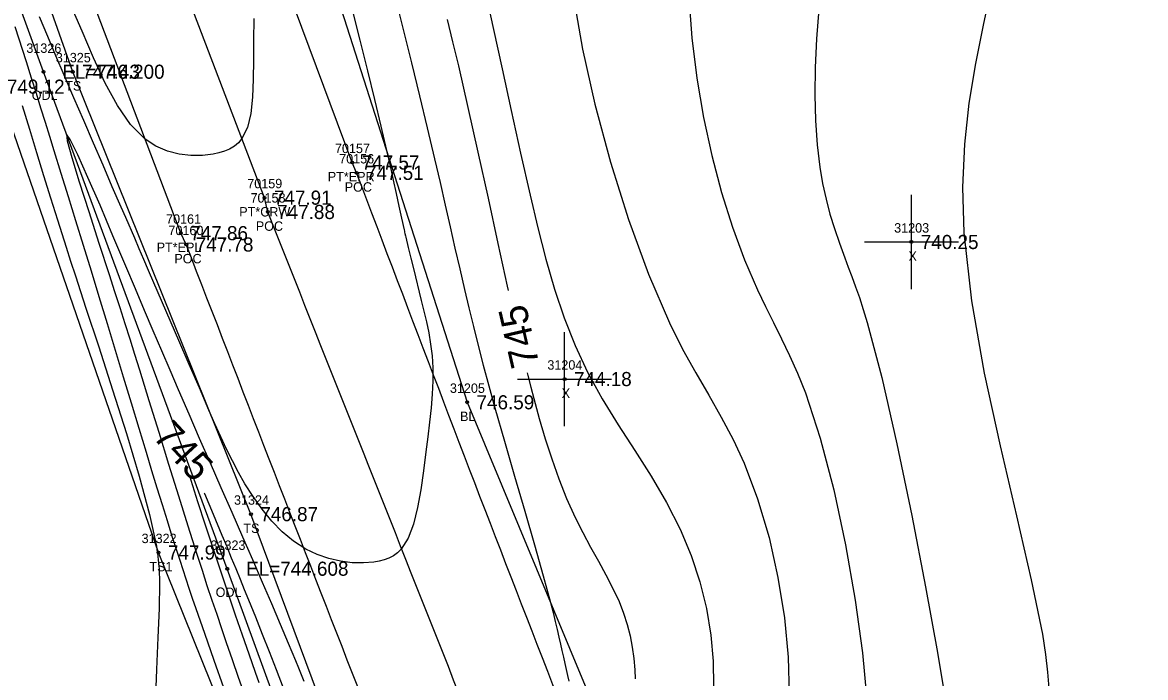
# Model space of a CAD drawing. Extents: x 1376587 to 1378239, y 1000335 to 1003031.
# Drawn here: x 1376751 to 1376870.4, y 1002682.8 to 1002752.4 of the extents above; entities that cross this region are included whole.
import ezdxf

# ---------------------------------------------------------------- set-up
doc = ezdxf.new("R2010")
doc.units = 0
for name, color, linetype in [('RD_DTM_BkLn1', 7, 'Continuous'), ('RD_DTM_BkLn2', 7, 'Continuous'), ('RD_DTM_BkLn_txCode', 7, 'Continuous'), ('RD_DTM_Major1', 7, 'Continuous'), ('RD_DTM_Major1_Lbl', 7, 'Continuous'), ('RD_DTM_Minor1', 7, 'Continuous'), ('RD_EX_H2O', 7, 'Continuous'), ('RD_EX_H2O_txCode', 7, 'Continuous'), ('RD_EX_Misc', 7, 'Continuous'), ('RD_EX_Misc_txCode', 7, 'Continuous'), ('RD_EX_Road', 7, 'Continuous'), ('RD_EX_Road_txCode', 7, 'Continuous'), ('RD_EX_TX_H2O_ELEV', 7, 'Continuous'), ('RD_EX_TX_Misc_ELEV', 7, 'Continuous'), ('RD_EX_TX_Road_ELEV', 7, 'Continuous'), ('RD_HC_Survey_ELEV', 7, 'Continuous'), ('RD_HC_Survey_txCode', 7, 'Continuous'), ('RD_SMD_Locator', 7, 'Continuous')]:
    doc.layers.add(name, color=color, linetype=linetype)

msp = doc.modelspace()

# ---------------------------------------------------------------- linework, layer by layer
at = {"layer": 'RD_DTM_BkLn1'}
for points in [[(1376777.12, 1002732.3), (1376776.77, 1002733.82), (1376754.91, 1002791.11), (1376734.25, 1002847.87), (1376712.48, 1002906.61), (1376690.98, 1002965.02), (1376668.66, 1003026.02)], [(1376775.36, 1002784.46), (1376784.04, 1002756.66), (1376798.31, 1002712.07), (1376818.41, 1002663.8), (1376823.91, 1002650.38)]]:
    msp.add_lwpolyline(points, dxfattribs=at)
msp.add_spline([(1377003.45, 1002259.31), (1376973.19, 1002311.2), (1376942.72, 1002364.73), (1376914.25, 1002420.14), (1376886.11, 1002475.59), (1376860.06, 1002531.09), (1376835.65, 1002585.09), (1376813.12, 1002641.26), (1376777.12, 1002732.3)], degree=3, dxfattribs=at)
at = {"layer": 'RD_DTM_BkLn2'}
for points in [[(1376885.61, 1002428.98), (1376889.78, 1002434.68), (1376874.69, 1002468.75), (1376852.19, 1002514.33), (1376831.8, 1002561.56), (1376809.96, 1002613.35), (1376792.97, 1002652.8), (1376775.33, 1002700.18), (1376756.39, 1002747.21), (1376739.8, 1002794.07), (1376723.1, 1002839.91), (1376704.95, 1002887.54), (1376687.77, 1002934.36), (1376670.41, 1002980.85)], [(1376885.61, 1002428.97), (1376881.3, 1002430.18), (1376863.13, 1002464.59), (1376838.71, 1002510.16), (1376821.82, 1002559.18), (1376802.89, 1002607.61), (1376786.81, 1002643.28), (1376765.51, 1002696.1), (1376748.39, 1002745.62), (1376732.07, 1002790.52), (1376713.54, 1002837.08), (1376692.71, 1002883.81), (1376675.42, 1002930.22), (1376657.29, 1002975.68)]]:
    msp.add_lwpolyline(points, dxfattribs=at)
at = {"layer": 'RD_DTM_Major1'}
for points in [[(1376854.11, 1002756.65), (1376853.2, 1002752.32), (1376852.36, 1002748.09), (1376851.65, 1002743.86), (1376851.16, 1002739.51), (1376850.95, 1002734.95), (1376851.09, 1002730.07), (1376851.91, 1002722.84), (1376853.28, 1002715.18), (1376854.96, 1002707.44), (1376856.71, 1002700), (1376858.28, 1002693.2), (1376859.46, 1002687.41), (1376859.79, 1002685.27), (1376860.01, 1002683.37), (1376860.13, 1002681.68)], [(1376796.2, 1002752.76), (1376796.77, 1002750.39), (1376797.38, 1002747.84), (1376798.39, 1002743.42), (1376799.45, 1002738.66), (1376800.53, 1002733.78), (1376801.59, 1002728.96), (1376802.58, 1002724.43), (1376802.69, 1002723.97)], [(1376804.69, 1002715.2), (1376804.76, 1002714.93), (1376805.07, 1002713.69), (1376805.39, 1002712.46), (1376805.97, 1002710.34), (1376806.61, 1002708.19), (1376807.3, 1002706.05), (1376808.06, 1002703.92), (1376808.89, 1002701.85), (1376809.79, 1002699.84), (1376810.6, 1002698.23), (1376811.44, 1002696.68), (1376812.27, 1002695.18), (1376813.07, 1002693.72), (1376813.81, 1002692.29), (1376814.46, 1002690.88), (1376814.94, 1002689.66), (1376815.32, 1002688.44), (1376815.63, 1002687.24), (1376815.86, 1002686.03), (1376816.03, 1002684.83), (1376816.14, 1002683.63), (1376816.18, 1002682.66)], [(1376768.87, 1002704.05), (1376768.94, 1002703.78), (1376769.66, 1002701.53), (1376770.47, 1002699.04), (1376771.31, 1002696.48), (1376772.13, 1002694.05), (1376772.91, 1002691.72), (1376773.67, 1002689.49), (1376774.41, 1002687.36), (1376775.11, 1002685.32), (1376775.78, 1002683.38), (1376776.16, 1002682.27)], [(1376778.8, 1002681.68), (1376778.04, 1002683.64), (1376777.29, 1002685.54), (1376776.56, 1002687.4), (1376775.84, 1002689.22), (1376775.11, 1002691.04), (1376774.66, 1002692.13), (1376774.21, 1002693.24), (1376773.75, 1002694.36), (1376773.28, 1002695.51), (1376772.79, 1002696.69), (1376772.28, 1002697.92), (1376771.35, 1002700.14), (1376770.42, 1002702.33), (1376770.39, 1002702.4)]]:
    msp.add_lwpolyline(points, dxfattribs=at)
at = {"layer": 'RD_DTM_Minor1'}
for points in [[(1376790.63, 1002755.26), (1376791.5, 1002751.71), (1376792.38, 1002748.16), (1376793.24, 1002744.66), (1376794.07, 1002741.24), (1376794.85, 1002737.95), (1376795.43, 1002735.45), (1376795.98, 1002733.04), (1376796.51, 1002730.72), (1376797.02, 1002728.46), (1376797.52, 1002726.25), (1376798.03, 1002724.07), (1376798.49, 1002722.12), (1376798.98, 1002720.14), (1376799.49, 1002718.12), (1376800.03, 1002716.02), (1376800.63, 1002713.82), (1376801.27, 1002711.48), (1376802.28, 1002707.93), (1376803.35, 1002704.22), (1376804.43, 1002700.49), (1376805.47, 1002696.9), (1376806.4, 1002693.62), (1376807.17, 1002690.8), (1376807.44, 1002689.73), (1376807.68, 1002688.77), (1376807.89, 1002687.9), (1376808.07, 1002687.1), (1376808.24, 1002686.37), (1376808.39, 1002685.67), (1376808.54, 1002684.98), (1376808.69, 1002684.31), (1376808.83, 1002683.66), (1376808.97, 1002683.03), (1376809.11, 1002682.42)], [(1376800.3, 1002755.46), (1376801.11, 1002751.7), (1376802.02, 1002747.51), (1376802.99, 1002743.07), (1376803.99, 1002738.54), (1376805, 1002734.1), (1376805.84, 1002730.6), (1376806.69, 1002727.27), (1376807.61, 1002724.09), (1376808.63, 1002721.05), (1376809.78, 1002718.11), (1376811.11, 1002715.27), (1376812.67, 1002712.45), (1376814.37, 1002709.69), (1376816.13, 1002706.95), (1376817.87, 1002704.2), (1376819.51, 1002701.42), (1376820.97, 1002698.57), (1376822.12, 1002695.8), (1376823.04, 1002692.98), (1376823.74, 1002690.14), (1376824.21, 1002687.32), (1376824.46, 1002684.56), (1376824.51, 1002681.88)], [(1376775.65, 1002752.85), (1376775.6, 1002750.53), (1376775.6, 1002748.44), (1376775.58, 1002746.41), (1376775.5, 1002744.49), (1376775.31, 1002742.76), (1376774.96, 1002741.27), (1376774.38, 1002740.1), (1376774, 1002739.65), (1376773.57, 1002739.28), (1376773.07, 1002738.99), (1376772.53, 1002738.76), (1376771.93, 1002738.58), (1376771.3, 1002738.44), (1376770.17, 1002738.31), (1376768.96, 1002738.3), (1376767.71, 1002738.44), (1376766.46, 1002738.76), (1376765.24, 1002739.29), (1376764.08, 1002740.04), (1376762.53, 1002741.6), (1376761.14, 1002743.62), (1376759.85, 1002746.01), (1376758.61, 1002748.67), (1376757.38, 1002751.51), (1376756.11, 1002754.43)], [(1376809.65, 1002754.92), (1376810.58, 1002749.61), (1376811.9, 1002743.75), (1376813.55, 1002737.61), (1376815.47, 1002731.49), (1376817.58, 1002725.69), (1376819.82, 1002720.5), (1376821.21, 1002717.73), (1376822.61, 1002715.2), (1376823.99, 1002712.81), (1376825.32, 1002710.48), (1376826.59, 1002708.1), (1376827.76, 1002705.59), (1376829.19, 1002701.79), (1376830.4, 1002697.7), (1376831.35, 1002693.44), (1376832.04, 1002689.14), (1376832.44, 1002684.96), (1376832.53, 1002681.02)], [(1376821.87, 1002755.12), (1376822.19, 1002750.82), (1376822.71, 1002746.51), (1376823.42, 1002742.35), (1376824.32, 1002738.29), (1376825.36, 1002734.38), (1376826.53, 1002730.67), (1376827.81, 1002727.21), (1376829.16, 1002724.04), (1376830.01, 1002722.26), (1376830.87, 1002720.54), (1376831.73, 1002718.83), (1376832.59, 1002717.06), (1376833.44, 1002715.17), (1376834.27, 1002713.09), (1376835.85, 1002708.26), (1376837.28, 1002702.75), (1376838.53, 1002696.9), (1376839.56, 1002691.02), (1376840.32, 1002685.43), (1376840.79, 1002680.44)], [(1376786.07, 1002753.94), (1376786.91, 1002750.55), (1376787.71, 1002747.31), (1376788.46, 1002744.25), (1376789.14, 1002741.41), (1376789.75, 1002738.82), (1376790.12, 1002737.19), (1376790.45, 1002735.68), (1376790.76, 1002734.27), (1376791.05, 1002732.92), (1376791.33, 1002731.64), (1376791.61, 1002730.4), (1376791.64, 1002730.27), (1376791.67, 1002730.14), (1376791.7, 1002730.01), (1376791.75, 1002729.76), (1376791.78, 1002729.63), (1376792.05, 1002728.51), (1376792.32, 1002727.4), (1376792.6, 1002726.28), (1376793.44, 1002722.9), (1376793.72, 1002721.77), (1376793.99, 1002720.61), (1376794.23, 1002719.44), (1376794.43, 1002718.24), (1376794.58, 1002717), (1376794.66, 1002715.73), (1376794.67, 1002714.36), (1376794.6, 1002712.95), (1376794.48, 1002711.49), (1376794.32, 1002709.97), (1376794.13, 1002708.41), (1376793.92, 1002706.8), (1376793.67, 1002704.79), (1376793.39, 1002702.78), (1376793.04, 1002700.87), (1376792.6, 1002699.12), (1376792.03, 1002697.62), (1376791.29, 1002696.46), (1376790.9, 1002696.07), (1376790.47, 1002695.76), (1376790, 1002695.51), (1376789.5, 1002695.32), (1376788.97, 1002695.18), (1376788.4, 1002695.08), (1376787.28, 1002694.99), (1376786.1, 1002695.02), (1376784.86, 1002695.17), (1376783.61, 1002695.46), (1376782.37, 1002695.88), (1376781.17, 1002696.45), (1376779.87, 1002697.29), (1376778.66, 1002698.3), (1376777.54, 1002699.45), (1376776.51, 1002700.7), (1376775.56, 1002702.04), (1376774.7, 1002703.41), (1376774.01, 1002704.61), (1376773.36, 1002705.84), (1376772.74, 1002707.1), (1376772.13, 1002708.41), (1376771.51, 1002709.79), (1376770.87, 1002711.24), (1376769.85, 1002713.59), (1376768.77, 1002716.08), (1376767.67, 1002718.65), (1376765.48, 1002723.72), (1376764.46, 1002726.09), (1376763.95, 1002727.26), (1376763.46, 1002728.39), (1376762.98, 1002729.5), (1376762.03, 1002731.7), (1376761.54, 1002732.82), (1376760.59, 1002734.99), (1376759.61, 1002737.26), (1376758.59, 1002739.61), (1376757.56, 1002742.01), (1376756.52, 1002744.42), (1376755.49, 1002746.83), (1376754.61, 1002748.91), (1376753.73, 1002750.97), (1376752.86, 1002753.04)], [(1376835.7, 1002753.87), (1376835.45, 1002750.7), (1376835.31, 1002747.66), (1376835.27, 1002744.77), (1376835.33, 1002742.02), (1376835.51, 1002739.45), (1376835.79, 1002737.06), (1376836.09, 1002735.32), (1376836.46, 1002733.67), (1376836.88, 1002732.08), (1376837.36, 1002730.53), (1376837.88, 1002728.99), (1376838.45, 1002727.43), (1376838.82, 1002726.45), (1376839.2, 1002725.44), (1376839.59, 1002724.36), (1376840, 1002723.2), (1376840.41, 1002721.93), (1376840.84, 1002720.54), (1376842.4, 1002714.69), (1376844, 1002707.66), (1376845.58, 1002700.05), (1376847.04, 1002692.45), (1376848.3, 1002685.47), (1376849.28, 1002679.7)], [(1376750.25, 1002752.02), (1376751.43, 1002748.3), (1376751.98, 1002746.56), (1376752.49, 1002744.93), (1376752.98, 1002743.37), (1376753.45, 1002741.85), (1376753.92, 1002740.35), (1376754.39, 1002738.83), (1376755.13, 1002736.44), (1376755.9, 1002733.96), (1376756.69, 1002731.39), (1376757.51, 1002728.76), (1376758.34, 1002726.06), (1376759.18, 1002723.31), (1376760.05, 1002720.46), (1376760.91, 1002717.61), (1376761.76, 1002714.78), (1376762.6, 1002712.01), (1376763.41, 1002709.33), (1376764.18, 1002706.77), (1376764.77, 1002704.83), (1376765.33, 1002702.99), (1376765.88, 1002701.21), (1376766.41, 1002699.5), (1376766.93, 1002697.85), (1376767.45, 1002696.24), (1376767.76, 1002695.27), (1376768.08, 1002694.3), (1376768.41, 1002693.32), (1376768.74, 1002692.31), (1376769.1, 1002691.26), (1376769.47, 1002690.16), (1376770.38, 1002687.52), (1376771.37, 1002684.67), (1376772.4, 1002681.74)], [(1376751.02, 1002743.62), (1376751.79, 1002741.12), (1376752.55, 1002738.63), (1376753.3, 1002736.19), (1376754.04, 1002733.79), (1376754.77, 1002731.45), (1376755.22, 1002730), (1376755.68, 1002728.55), (1376756.16, 1002727.06), (1376756.67, 1002725.51), (1376757.2, 1002723.86), (1376757.79, 1002722.09), (1376759.15, 1002717.95), (1376760.63, 1002713.41), (1376762.11, 1002708.74), (1376763.45, 1002704.23), (1376764.55, 1002700.14), (1376765.28, 1002696.76), (1376765.34, 1002696.38), (1376765.39, 1002696.02), (1376765.44, 1002695.67), (1376765.48, 1002695.33), (1376765.51, 1002694.99), (1376765.54, 1002694.66), (1376765.56, 1002694.36), (1376765.58, 1002694.07), (1376765.59, 1002693.77), (1376765.6, 1002693.47), (1376765.61, 1002693.16), (1376765.61, 1002692.85), (1376765.57, 1002690.15), (1376765.44, 1002687.07), (1376765.28, 1002683.65), (1376765.14, 1002679.96)], [(1376780.99, 1002682.39), (1376780.71, 1002683.09), (1376780.41, 1002683.82), (1376780.1, 1002684.58), (1376779.33, 1002686.43), (1376778.47, 1002688.45), (1376777.54, 1002690.63), (1376776.55, 1002692.92), (1376775.52, 1002695.31), (1376774.46, 1002697.74), (1376773.32, 1002700.34), (1376772.17, 1002702.96), (1376771.03, 1002705.59), (1376769.88, 1002708.21), (1376768.75, 1002710.82), (1376767.63, 1002713.4), (1376766.74, 1002715.47), (1376765.85, 1002717.54), (1376764.95, 1002719.66), (1376764.03, 1002721.84), (1376763.06, 1002724.13), (1376762.03, 1002726.55), (1376760.66, 1002729.78), (1376759.29, 1002733.01), (1376758.01, 1002735.96), (1376756.92, 1002738.39), (1376756.13, 1002740.01), (1376755.73, 1002740.58), (1376755.81, 1002739.88), (1376756.3, 1002738.09), (1376757.09, 1002735.49), (1376758.09, 1002732.36), (1376759.18, 1002729), (1376760.26, 1002725.67), (1376760.84, 1002723.86), (1376761.4, 1002722.13), (1376761.93, 1002720.46), (1376762.45, 1002718.82), (1376762.96, 1002717.18), (1376763.48, 1002715.52), (1376764.49, 1002712.25), (1376765.53, 1002708.88), (1376766.58, 1002705.49), (1376767.62, 1002702.14), (1376768.63, 1002698.93), (1376769.58, 1002695.93), (1376770.13, 1002694.22), (1376770.66, 1002692.6), (1376771.18, 1002691.04), (1376771.69, 1002689.53), (1376772.2, 1002688.04), (1376772.71, 1002686.55), (1376773.34, 1002684.72), (1376773.99, 1002682.86), (1376774.65, 1002680.98)]]:
    msp.add_lwpolyline(points, dxfattribs=at)
at = {"layer": 'RD_EX_H2O'}
msp.add_lwpolyline([(1376884.04, 1002432.1), (1376867.96, 1002466.27), (1376845.47, 1002511.58), (1376827.22, 1002560.38), (1376806.48, 1002611.18), (1376788.41, 1002651.65), (1376772.82, 1002694.38), (1376753.28, 1002747.21), (1376736.65, 1002792.89), (1376719.2, 1002838.91), (1376701.08, 1002887.18), (1376684.58, 1002932.85), (1376667.2, 1002979.87)], dxfattribs=at)
at = {"layer": 'RD_EX_Misc'}
for p, q in [((1376845.53, 1002724.11), (1376845.53, 1002734.11)), ((1376840.53, 1002729.11), (1376850.53, 1002729.11)), ((1376808.67, 1002709.54), (1376808.67, 1002719.54)), ((1376803.67, 1002714.54), (1376813.67, 1002714.54))]:
    msp.add_line(p, q, dxfattribs=at)
at = {"layer": 'RD_EX_Road'}
for points in [[(1376786.56, 1002736.46), (1376786.1, 1002737.56), (1376764.69, 1002795), (1376744.07, 1002850.85), (1376722.32, 1002910.05), (1376701.33, 1002967.35), (1376678.41, 1003028.92)], [(1376768.46, 1002728.84), (1376767.88, 1002730.05), (1376746.2, 1002787.1), (1376725.11, 1002844.98), (1376703.8, 1002902.78), (1376682.09, 1002961.91), (1376659.76, 1003022.67)]]:
    msp.add_lwpolyline(points, dxfattribs=at)
for points in [[(1377013.31, 1002264.91), (1376982.81, 1002315.68), (1376952.47, 1002370.34), (1376923.17, 1002424.32), (1376895.64, 1002480.03), (1376870.11, 1002535.05), (1376846.33, 1002588.86), (1376822.29, 1002645.03), (1376786.56, 1002736.46)], [(1376994.75, 1002253.91), (1376964.91, 1002306.46), (1376934.4, 1002359.99), (1376904.77, 1002415.49), (1376877.27, 1002471.51), (1376851.04, 1002526.89), (1376827.48, 1002581.62), (1376804.19, 1002637.82), (1376768.46, 1002728.84)]]:
    msp.add_spline(points, degree=3, dxfattribs=at)
at = {"layer": 'RD_SMD_Locator'}
for centre in [(1376753.28, 1002747.21), (1376756.39, 1002747.21), (1376786.1, 1002737.56), (1376786.56, 1002736.46), (1376776.77, 1002733.82), (1376777.12, 1002732.3), (1376767.88, 1002730.05), (1376768.46, 1002728.84), (1376845.53, 1002729.11), (1376808.67, 1002714.54), (1376798.31, 1002712.07), (1376775.33, 1002700.18), (1376765.51, 1002696.1), (1376772.82, 1002694.38)]:
    msp.add_circle(centre, 0.15, dxfattribs=at)

# ---------------------------------------------------------------- texts
at = {"layer": 'RD_DTM_BkLn_txCode'}
for s, p in [('31325', (1376754.59, 1002748.21)), ('TS', (1376755.59, 1002745.21)), ('31205', (1376796.48, 1002713.07)), ('BL', (1376797.56, 1002710.07)), ('31324', (1376773.53, 1002701.18)), ('TS', (1376774.53, 1002698.18)), ('31322', (1376763.71, 1002697.1)), ('TS1', (1376764.54, 1002694.1))]:
    msp.add_text(s, height=1, dxfattribs=at).set_placement(p)
at = {"layer": 'RD_DTM_Major1_Lbl'}
for rotation, p in [(102.8984, (1376806, 1002716.12)), (312.8181, (1376764.79, 1002708.35))]:
    msp.add_text('745', height=3, rotation=rotation, dxfattribs=at).set_placement(p)
at = {"layer": 'RD_EX_H2O_txCode'}
for s, p in [('31326', (1376751.46, 1002749.21)), ('ODL', (1376752.03, 1002744.21)), ('31323', (1376771.03, 1002696.38)), ('ODL', (1376771.58, 1002691.38))]:
    msp.add_text(s, height=1, dxfattribs=at).set_placement(p)
at = {"layer": 'RD_EX_Misc_txCode'}
for s, p in [('31203', (1376843.7, 1002730.11)), ('X', (1376845.22, 1002727.11)), ('31204', (1376806.84, 1002715.54)), ('X', (1376808.36, 1002712.54))]:
    msp.add_text(s, height=1, dxfattribs=at).set_placement(p)
at = {"layer": 'RD_EX_Road_txCode'}
for s, p in [('70157', (1376784.26, 1002738.56)), ('70156', (1376784.71, 1002737.46)), ('PT*EPR', (1376783.5, 1002735.56)), ('POC', (1376785.3, 1002734.46)), ('70161', (1376766.31, 1002731.05)), ('70160', (1376766.56, 1002729.84)), ('PT*EPL', (1376765.31, 1002728.05)), ('POC', (1376767.19, 1002726.84))]:
    msp.add_text(s, height=1, dxfattribs=at).set_placement(p)
at = {"layer": 'RD_EX_TX_H2O_ELEV'}
for s, p in [('EL=746.200', (1376755.28, 1002746.46)), ('EL=744.608', (1376774.82, 1002693.63))]:
    msp.add_text(s, height=1.5, dxfattribs=at).set_placement(p)
at = {"layer": 'RD_EX_TX_Misc_ELEV'}
for s, p in [('747.43', (1376757.39, 1002746.46)), ('749.12', (1376749.39, 1002744.87)), ('740.25', (1376846.53, 1002728.36)), ('744.18', (1376809.67, 1002713.79)), ('746.59', (1376799.31, 1002711.32)), ('746.87', (1376776.33, 1002699.43)), ('747.99', (1376766.51, 1002695.35))]:
    msp.add_text(s, height=1.5, dxfattribs=at).set_placement(p)
at = {"layer": 'RD_EX_TX_Road_ELEV'}
for s, p in [('747.57', (1376787.1, 1002736.81)), ('747.51', (1376787.56, 1002735.71)), ('747.86', (1376768.88, 1002729.3)), ('747.78', (1376769.46, 1002728.09))]:
    msp.add_text(s, height=1.5, dxfattribs=at).set_placement(p)
at = {"layer": 'RD_HC_Survey_ELEV'}
for s, p in [('747.91', (1376777.77, 1002733.07)), ('747.88', (1376778.12, 1002731.55))]:
    msp.add_text(s, height=1.5, dxfattribs=at).set_placement(p)
at = {"layer": 'RD_HC_Survey_txCode'}
for s, p in [('70159', (1376774.94, 1002734.82)), ('70158', (1376775.29, 1002733.3)), ('PT*CRW', (1376774.09, 1002731.82)), ('POC', (1376775.85, 1002730.3))]:
    msp.add_text(s, height=1, dxfattribs=at).set_placement(p)

doc.saveas('drawing.dxf')
